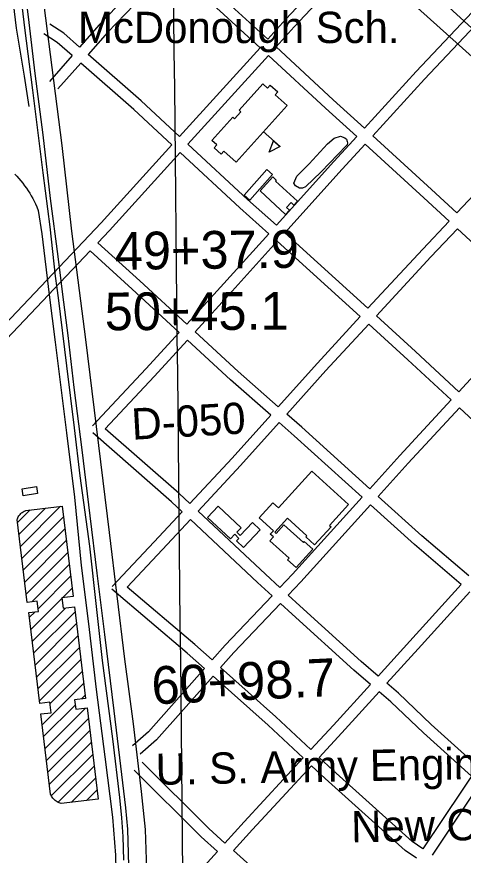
# Model space of a CAD drawing. Extents: x 3651524 to 3689615, y 505651 to 531377.
# Drawn here: x 3660475 to 3661657, y 523666 to 525888 of the extents above; entities that cross this region are included whole.
import ezdxf

# ---------------------------------------------------------------- set-up
doc = ezdxf.new("R2010")
doc.units = 0
for name, color, linetype in [('V-BLDG-IDEN', 7, 'Continuous'), ('V-BLDG-OTLN', 7, 'Continuous'), ('V-GRID-MAJR', 7, 'Continuous'), ('V-RAIL-TRAK', 7, 'Continuous'), ('V-RIVR-RANG-IDEN', 7, 'Continuous'), ('V-ROAD-CNTR', 7, 'Continuous'), ('V-SITE-VEGE', 7, 'Continuous'), ('V-SURV-IDEN', 7, 'Continuous'), ('V-TOPO-GNAM-IDEN', 7, 'Continuous'), ('V-TOPO-SHOR', 7, 'Continuous')]:
    doc.layers.add(name, color=color, linetype=linetype)

msp = doc.modelspace()

# ---------------------------------------------------------------- linework, layer by layer
at = {"layer": 'V-BLDG-OTLN'}
for p, q in [((3661126.927, 525583.749), (3661171.719, 525543.828)), ((3660484.122, 524484.047), (3660590.628, 524590.552)), ((3660476.473, 524547.108), (3660510.246, 524580.881)), ((3660480.298, 524515.577), (3660550.437, 524585.717)), ((3660487.947, 524452.516), (3660598.155, 524562.724)), ((3660491.772, 524420.985), (3660601.952, 524531.165)), ((3660495.597, 524389.455), (3660605.748, 524499.607)), ((3660499.422, 524357.924), (3660609.545, 524468.048)), ((3660514.131, 524337.278), (3660613.342, 524436.489)), ((3660531.327, 524319.119), (3660617.139, 524404.931)), ((3660595.598, 524348.034), (3660620.936, 524373.372)), ((3660511.486, 524263.923), (3660594.316, 524346.753)), ((3660507.661, 524295.454), (3660522.886, 524310.678)), ((3660515.311, 524232.392), (3660603.728, 524320.81)), ((3660519.135, 524200.861), (3660629.277, 524311.003)), ((3660522.96, 524169.331), (3660633.074, 524279.445)), ((3660526.785, 524137.8), (3660636.871, 524247.886)), ((3660530.609, 524106.269), (3660640.667, 524216.327)), ((3660534.434, 524074.739), (3660644.464, 524184.769)), ((3660562.589, 524067.538), (3660648.26, 524153.21)), ((3660541.824, 524011.418), (3660652.057, 524121.651)), ((3660645.854, 524080.093), (3660655.854, 524090.093)), ((3660545.649, 523979.887), (3660629.165, 524063.403)), ((3660549.474, 523948.357), (3660656.564, 524055.448)), ((3660553.298, 523916.827), (3660664.127, 524027.655)), ((3660557.123, 523885.296), (3660667.924, 523996.096)), ((3660560.948, 523853.766), (3660671.72, 523964.538)), ((3660565.957, 523823.419), (3660675.517, 523932.979)), ((3660583.578, 523805.685), (3660679.314, 523901.421)), ((3660618.867, 523805.618), (3660683.111, 523869.862)), ((3660659.057, 523810.453), (3660686.907, 523838.304))]:
    msp.add_line(p, q, dxfattribs=at)
for points in [[(3661145.851, 525707.163), (3661165.746, 525689.296), (3661158.428, 525681.149), (3661190.363, 525652.469), (3661055.649, 525502.471), (3661022.959, 525531.829), (3661015.9, 525523.969), (3660997.377, 525540.607), (3661004.375, 525548.398), (3660990.971, 525560.434), (3661046.343, 525622.087), (3661050.916, 525617.978), (3661067.523, 525636.468), (3661063.131, 525640.414), (3661126.154, 525710.587), (3661138.759, 525699.266)], [(3661171.719, 525543.828), (3661143.135, 525529.118), (3661154.473, 525559.199)], [(3661076.473, 525414.77), (3661136.764, 525482.839), (3661151.663, 525469.642), (3661091.37, 525401.574)], [(3661186.078, 525364.381), (3661118.631, 525426.433), (3661152.778, 525463.547), (3661161.678, 525455.357), (3661159.26, 525452.727), (3661217.642, 525399.014), (3661208.438, 525389.01), (3661201.104, 525395.758), (3661188.917, 525382.512), (3661196.412, 525375.614)], [(3661255.507, 524683.609), (3661353.119, 524594.953), (3661302.923, 524539.684), (3661306.736, 524536.221), (3661263.077, 524488.152), (3661239.594, 524509.48), (3661242.208, 524512.355), (3661191.3, 524558.591), (3661157.875, 524521.786), (3661161.156, 524518.809), (3661182.005, 524541.765), (3661233.825, 524494.699), (3661235.961, 524497.046), (3661258.577, 524476.507), (3661214.408, 524427.875), (3661191.798, 524448.413), (3661195.712, 524452.72), (3661144.528, 524499.205), (3661153.931, 524509.556), (3661145.958, 524516.797), (3661153.947, 524525.594), (3661116.389, 524559.705), (3661152.946, 524599.954), (3661167.513, 524586.724)], [(3660529.788, 524624.082), (3660491.306, 524618.266), (3660488.464, 524637.072), (3660526.948, 524642.889)], [(3660594.747, 524591.048), (3660623.579, 524351.401), (3660594.182, 524347.864), (3660597.528, 524320.064), (3660627.75, 524323.698), (3660656.897, 524081.421), (3660627.423, 524077.876), (3660630.499, 524052.313), (3660660.723, 524055.948), (3660689.813, 523814.153), (3660592.312, 523802.424), (3660589.41, 523803.252), (3660586.575, 523804.294), (3660583.829, 523805.547), (3660581.183, 523807.004), (3660578.654, 523808.654), (3660576.253, 523810.487), (3660573.998, 523812.498), (3660571.897, 523814.671), (3660569.968, 523816.996), (3660568.219, 523819.458), (3660566.654, 523822.042), (3660565.29, 523824.739), (3660564.131, 523827.529), (3660538.361, 524039.962), (3660565.532, 524043.257), (3660562.136, 524071.273), (3660535.25, 524068.011), (3660506.062, 524308.639), (3660532.213, 524311.809), (3660528.908, 524339.07), (3660502.103, 524335.82), (3660475.504, 524555.093), (3660476.317, 524557.657), (3660477.327, 524560.156), (3660478.525, 524562.562), (3660479.907, 524564.876), (3660481.464, 524567.074), (3660483.184, 524569.144), (3660485.06, 524571.076), (3660487.079, 524572.855), (3660489.23, 524574.475), (3660491.501, 524575.925), (3660493.877, 524577.193), (3660496.34, 524578.272), (3660498.882, 524579.161), (3660498.841, 524579.509)], [(3661119.34, 524528.422), (3661075.044, 524481.394), (3661056.608, 524498.757), (3661062.985, 524505.527), (3661051.668, 524516.187), (3661040.193, 524504.004), (3660979.582, 524561.092), (3661007.677, 524590.919), (3661068.459, 524533.669), (3661057.128, 524521.633), (3661066.45, 524512.851), (3661099.085, 524547.499)]]:
    msp.add_lwpolyline(points, close=True, dxfattribs=at)
at = {"layer": 'V-GRID-MAJR'}
msp.add_spline([(3661045.474, 511119.283), (3660982.023, 517177.978), (3660918.553, 523238.605), (3660855.082, 529299.245), (3660855.062, 529301.164)], degree=3, dxfattribs=at)
at = {"layer": 'V-RAIL-TRAK'}
for points in [[(3660773.914, 523541.374), (3660768.47, 523734.547), (3660763.567, 523791.318), (3660750.161, 523901.38), (3660732.09, 524048.131), (3660707.913, 524250.494), (3660687.763, 524413.226), (3660668.602, 524565.31), (3660648.068, 524739.855), (3660626.777, 524904.969), (3660610.91, 525042.824), (3660596.891, 525151.716), (3660593.127, 525180.894), (3660583.909, 525252.322), (3660564.191, 525406.189), (3660544.745, 525575.402), (3660523.411, 525738.155), (3660505.39, 525887.858), (3660483.719, 526064.786), (3660462.458, 526231.67)], [(3660473.804, 526038.392), (3660495.435, 525859.102), (3660516.126, 525693.408), (3660543.551, 525474.457), (3660561.686, 525331.246), (3660576.497, 525200.494), (3660580.491, 525168.885), (3660583.749, 525143.092), (3660605.949, 524962.612), (3660626.661, 524798.1), (3660641.548, 524671.479), (3660667.185, 524485.035), (3660685.016, 524324.705), (3660700.79, 524181.538), (3660727.824, 523973.809), (3660746.329, 523818.194), (3660751.873, 523764.364), (3660755.14, 523715.298), (3660757.565, 523652.079)]]:
    msp.add_lwpolyline(points, dxfattribs=at)
at = {"layer": 'V-ROAD-CNTR'}
for points in [[(3660141.295, 529270.676), (3660140.146, 529257.885), (3660207.54, 528672.889), (3660264.536, 528198.301), (3660307.434, 527853.775), (3660381.584, 527230.666), (3660444.851, 526759.634), (3660523.843, 526091.959), (3660593.844, 525547.214), (3660619.118, 525319.853), (3660656.441, 525032.649), (3660719.252, 524520.83), (3660759.714, 524185.351), (3660783.113, 524013.914), (3660804.031, 523834.787), (3660814.113, 523733.801), (3660817.382, 523654.494), (3660819.82, 523527.387), (3660822.74, 523322.401), (3660825.188, 523004.512), (3660829.644, 522672.085), (3660834.768, 522247.179), (3660840.69, 521789.439), (3660851.979, 521389.387)], [(3663344.161, 524443.476), (3662896.215, 524797.415), (3661850.172, 525702.548), (3660405.103, 527021.233), (3660409.707, 527021.285)], [(3660424.509, 526911.081), (3660424.472, 526911.359), (3660464.142, 526879.962), (3660704.384, 526669.45), (3661468.044, 525973.317), (3661953.079, 525537.429), (3663053.119, 524600.942), (3663202.07, 524489.981)], [(3661138.926, 525828.368), (3661187.19, 525881.628), (3661402.566, 526111.284)], [(3661395.006, 525592.784), (3661532.053, 525742.91), (3661785.226, 526012.084), (3661867.134, 526104.782)], [(3661160.978, 525808.026), (3661209.248, 525861.294), (3661424.448, 526090.762)], [(3661417.143, 525572.536), (3661554.059, 525722.519), (3661807.398, 525991.87), (3661889.367, 526084.638)], [(3660858.946, 526039.987), (3660692.92, 525866.556), (3660641.057, 525807.752)], [(3661138.927, 525828.368), (3661032.76, 525926.303), (3660902.197, 526041.782)], [(3660881.435, 526020.096), (3660715.014, 525846.252), (3660663.625, 525787.985)], [(3661118.781, 525806.137), (3661012.65, 525904.039), (3660881.435, 526020.095)], [(3662111.228, 525885.907), (3661807.9, 525545.814), (3661640.049, 525368.149)], [(3660641.057, 525807.752), (3660599.427, 525844.213), (3660562.174, 525868.257)], [(3660621.214, 525785.252), (3660581.313, 525820.199), (3660546.274, 525842.813)], [(3660905.602, 525570.889), (3661118.781, 525806.137)], [(3661395.006, 525592.784), (3661312.62, 525668.142), (3661160.978, 525808.026)], [(3660621.214, 525785.252), (3660560.808, 525716.761)], [(3660905.603, 525570.889), (3660804.178, 525664.881), (3660663.625, 525787.985)], [(3660927.607, 525550.496), (3661140.832, 525785.795)], [(3661374.78, 525570.627), (3661292.326, 525646.048), (3661140.833, 525785.795)], [(3660643.782, 525765.484), (3660583.308, 525696.917)], [(3660885.458, 525548.657), (3660784.096, 525642.591), (3660643.782, 525765.484)], [(3661161.886, 525335.294), (3661314.173, 525504.236), (3661374.78, 525570.627)], [(3661640.049, 525368.148), (3661572.537, 525430.396), (3661417.143, 525572.536)], [(3660442.891, 525072.481), (3660698.088, 525341.89), (3660885.457, 525548.658)], [(3661161.887, 525335.294), (3661085.639, 525404.047), (3660927.608, 525550.496)], [(3661184.166, 525315.204), (3661336.393, 525484.08), (3661396.916, 525550.379)], [(3661619.445, 525346.34), (3661552.245, 525408.3), (3661396.916, 525550.379)], [(3660689.32, 525289.009), (3660720.096, 525321.5), (3660907.462, 525528.265)], [(3661141.801, 525313.011), (3661065.397, 525381.903), (3660907.462, 525528.265)], [(3660469.483, 525471.124), (3660475.004, 525465.255), (3660480.364, 525459.236), (3660485.558, 525453.069), (3660490.581, 525446.761), (3660495.433, 525440.318), (3660500.109, 525433.744), (3660504.602, 525427.043), (3660508.911, 525420.221), (3660513.034, 525413.285), (3660516.966, 525406.236), (3660520.703, 525399.084), (3660524.244, 525391.83), (3660527.589, 525384.482), (3660530.962, 525374.975), (3660540.491, 525312.81), (3660560.715, 525150.85), (3660576.161, 525025.809), (3660606.152, 524784.965), (3660627.349, 524614.538)], [(3661619.445, 525346.341), (3661549.406, 525272.207), (3661404.56, 525115.343)], [(3661641.502, 525326.004), (3661571.33, 525251.729), (3661426.747, 525095.15)], [(3661858.964, 525126.026), (3661799.987, 525179.877), (3661641.502, 525326.003)], [(3660924.716, 525073.554), (3661022.571, 525180.744), (3661141.8, 525313.011)], [(3661404.561, 525115.342), (3661270.711, 525237.167), (3661184.167, 525315.204)], [(3660924.718, 525073.554), (3660800.46, 525188.482), (3660689.32, 525289.009)], [(3660946.741, 525053.184), (3661044.791, 525160.588), (3661164.08, 525292.921)], [(3661384.208, 525093.301), (3661250.569, 525214.934), (3661164.081, 525292.921)], [(3660447.462, 525033.682), (3660668.683, 525267.224)], [(3660904.491, 525051.398), (3660780.212, 525166.344), (3660668.683, 525267.224)], [(3661858.964, 525126.026), (3661644.896, 524894.327)], [(3661384.208, 525093.303), (3661270.631, 524970.301), (3661166.974, 524854.529)], [(3661644.896, 524894.327), (3661530.674, 525000.558), (3661426.747, 525095.149)], [(3661406.395, 525073.109), (3661292.827, 524950.119), (3661189.525, 524834.741)], [(3661624.538, 524872.291), (3661510.362, 524978.48), (3661406.394, 525073.108)], [(3660674.825, 524803.954), (3660816.638, 524955.166), (3660904.49, 525051.398)], [(3661166.975, 524854.528), (3661060.701, 524947.782), (3660946.742, 525053.184)], [(3660708.661, 524796.178), (3660838.658, 524934.79), (3660926.514, 525031.028)], [(3661146.963, 524832.176), (3661040.619, 524925.492), (3660926.515, 525031.028)], [(3661624.538, 524872.291), (3661488.817, 524725.394), (3661409.139, 524637.004)], [(3661409.139, 524637.003), (3661229.308, 524799.831), (3661189.525, 524834.74)], [(3661646.506, 524851.86), (3661510.977, 524705.17), (3661431.376, 524616.867)], [(3661878.979, 524635.65), (3661646.506, 524851.86)], [(3661146.962, 524832.177), (3661045.104, 524718.416), (3660933.066, 524597.746)], [(3661169.513, 524812.39), (3661067.274, 524698.202), (3660954.936, 524577.211)], [(3661389.052, 524614.72), (3661209.346, 524777.435), (3661169.513, 524812.388)], [(3660933.066, 524597.746), (3660904.846, 524624.243), (3660708.661, 524796.178)], [(3660912.653, 524575.76), (3660884.686, 524602.021), (3660675.522, 524785.331)], [(3660627.349, 524614.538), (3660645.482, 524433.343), (3660664.08, 524278.576), (3660684.66, 524104.758), (3660707.487, 523926.728), (3660727.85, 523766.828), (3660735.809, 523666.046), (3660737.628, 523585.316), (3660737.607, 523479.111), (3660739.051, 523377.053), (3660739.96, 523244.858), (3660742.354, 523144.177), (3660742.387, 523014.782), (3660742.412, 522884.922), (3660743.12, 522767.574), (3660745.228, 522650.664), (3660745.723, 522521.259)], [(3661389.052, 524614.721), (3661204.911, 524410.447), (3661171.318, 524375.057)], [(3661671.458, 524405.87), (3661547.122, 524512.065), (3661431.377, 524616.867)], [(3661411.29, 524594.584), (3661226.935, 524390.073), (3661193.482, 524354.83)], [(3661651.343, 524383.598), (3661527.308, 524489.535), (3661411.29, 524594.584)], [(3660912.653, 524575.762), (3660838.778, 524496.195), (3660727.462, 524377.78)], [(3661171.318, 524375.057), (3661132.733, 524410.266), (3660954.936, 524577.21)], [(3660934.524, 524555.226), (3660860.7, 524475.715), (3660766.933, 524375.968)], [(3661150.66, 524353.293), (3661112.353, 524388.25), (3660934.524, 524555.225)], [(3660971.865, 524160.581), (3660926.028, 524201.553), (3660726.214, 524371.184)], [(3660991.72, 524183.072), (3660945.736, 524224.175), (3660766.933, 524375.968)], [(3661431.523, 524140.631), (3661515.332, 524233.004), (3661651.342, 524383.598)], [(3661150.66, 524353.293), (3661026.757, 524222.762), (3660991.719, 524183.072)], [(3661431.523, 524140.631), (3661386.693, 524178.671), (3661223.992, 524326.989), (3661193.482, 524354.83)], [(3661454.41, 524121.211), (3661537.574, 524212.87), (3661674.162, 524364.107)], [(3661172.824, 524333.067), (3661048.889, 524202.502), (3661014.087, 524163.079)], [(3661411.354, 524118.401), (3661366.877, 524156.141), (3661203.776, 524304.823), (3661172.824, 524333.067)], [(3660971.865, 524160.582), (3660823.487, 523992.503), (3660781.36, 523955.673)], [(3661253.452, 523945.456), (3661160.245, 524032.432), (3661014.087, 524163.079)], [(3660994.233, 524140.589), (3660844.693, 523971.195), (3660801.106, 523933.087)], [(3661233.111, 523923.404), (3661140.013, 524010.28), (3660994.232, 524140.588)], [(3661253.452, 523945.456), (3661313.506, 524010.556), (3661411.354, 524118.401)], [(3661695.781, 523900.64), (3661571.778, 524012.379), (3661485.484, 524094.843), (3661454.41, 524121.211)], [(3661275.387, 523924.988), (3661335.64, 523990.306), (3661434.241, 524098.98)], [(3661678.886, 523875.481), (3661551.37, 523990.387), (3661465.398, 524072.541), (3661434.241, 524098.98)], [(3661025.796, 523697.775), (3661076.864, 523754.024), (3661233.111, 523923.404)], [(3661549.811, 523682.537), (3661521.376, 523702.074), (3661311.669, 523891.132), (3661275.387, 523924.988)], [(3661025.796, 523697.775), (3660983.258, 523736.02), (3660806.807, 523912.444)], [(3661048.106, 523677.717), (3661098.996, 523733.771), (3661255.044, 523902.937)], [(3661533.139, 523657.593), (3661502.758, 523678.468), (3661291.389, 523869.022), (3661255.044, 523902.937)], [(3661742.904, 523917.003), (3661680.714, 523824.39), (3661574.539, 523665.548)], [(3661005.63, 523675.563), (3660962.608, 523714.242), (3660785.595, 523891.23)], [(3661678.886, 523875.482), (3661655.79, 523841.088), (3661549.811, 523682.537)], [(3661359.976, 523398.533), (3661335.66, 523417.953), (3661170.916, 523567.305), (3661048.106, 523677.717)], [(3660809.055, 523449.183), (3660909.645, 523569.838), (3661005.63, 523675.563)]]:
    msp.add_lwpolyline(points, dxfattribs=at)
at = {"layer": 'V-SITE-VEGE'}
msp.add_lwpolyline([(3661347.053, 525545.893), (3661280.833, 525476.746), (3661239.365, 525437.3), (3661231.032, 525433.902), (3661223.343, 525433.447), (3661212.225, 525439.552), (3661208.225, 525447.304), (3661216.229, 525465.48), (3661248.72, 525498.586), (3661296.916, 525550.915), (3661314.92, 525566.551), (3661332.143, 525571.562), (3661343.293, 525567.231), (3661347.364, 525563.612), (3661349.613, 525557.073), (3661350.141, 525553.52), (3661349.455, 525548.213)], close=True, dxfattribs=at)
at = {"layer": 'V-TOPO-SHOR'}
msp.add_lwpolyline([(3660507.57, 525650.105), (3660494.856, 525731.075), (3660474.103, 525857.57), (3660458.657, 525983.968), (3660444.186, 526065.559), (3660424.765, 526167.274), (3660408.239, 526265.992), (3660395.681, 526355.799), (3660382.617, 526450.333), (3660378.888, 526472.793)], dxfattribs=at)

# ---------------------------------------------------------------- texts
at = {"layer": 'V-BLDG-IDEN'}
msp.add_text('McDonough Sch.', height=82.99983, dxfattribs=at).set_placement((3660636.737, 525818.397))
at = {"layer": 'V-RIVR-RANG-IDEN'}
msp.add_text('D-050', height=83, rotation=3.224326, dxfattribs=at).set_placement((3660780.577, 524766.744))
at = {"layer": 'V-SURV-IDEN'}
for s, rotation, p in [('49+37.9', 0.642802, (3660734.661, 525217.326)), ('50+45.1', 0.18599, (3660707.534, 525057.045)), ('60+98.7', 2.6875, (3660833.696, 524065.297))]:
    msp.add_text(s, height=100, rotation=rotation, dxfattribs=at).set_placement(p)
at = {"layer": 'V-TOPO-GNAM-IDEN'}
for s, p in [('U. S. Army Engineer District,', (3660842.883, 523851.913)), ('New Orleans', (3661360.71, 523699.586))]:
    msp.add_text(s, height=82.99983, rotation=1.0368, dxfattribs=at).set_placement(p)

doc.saveas('drawing.dxf')
